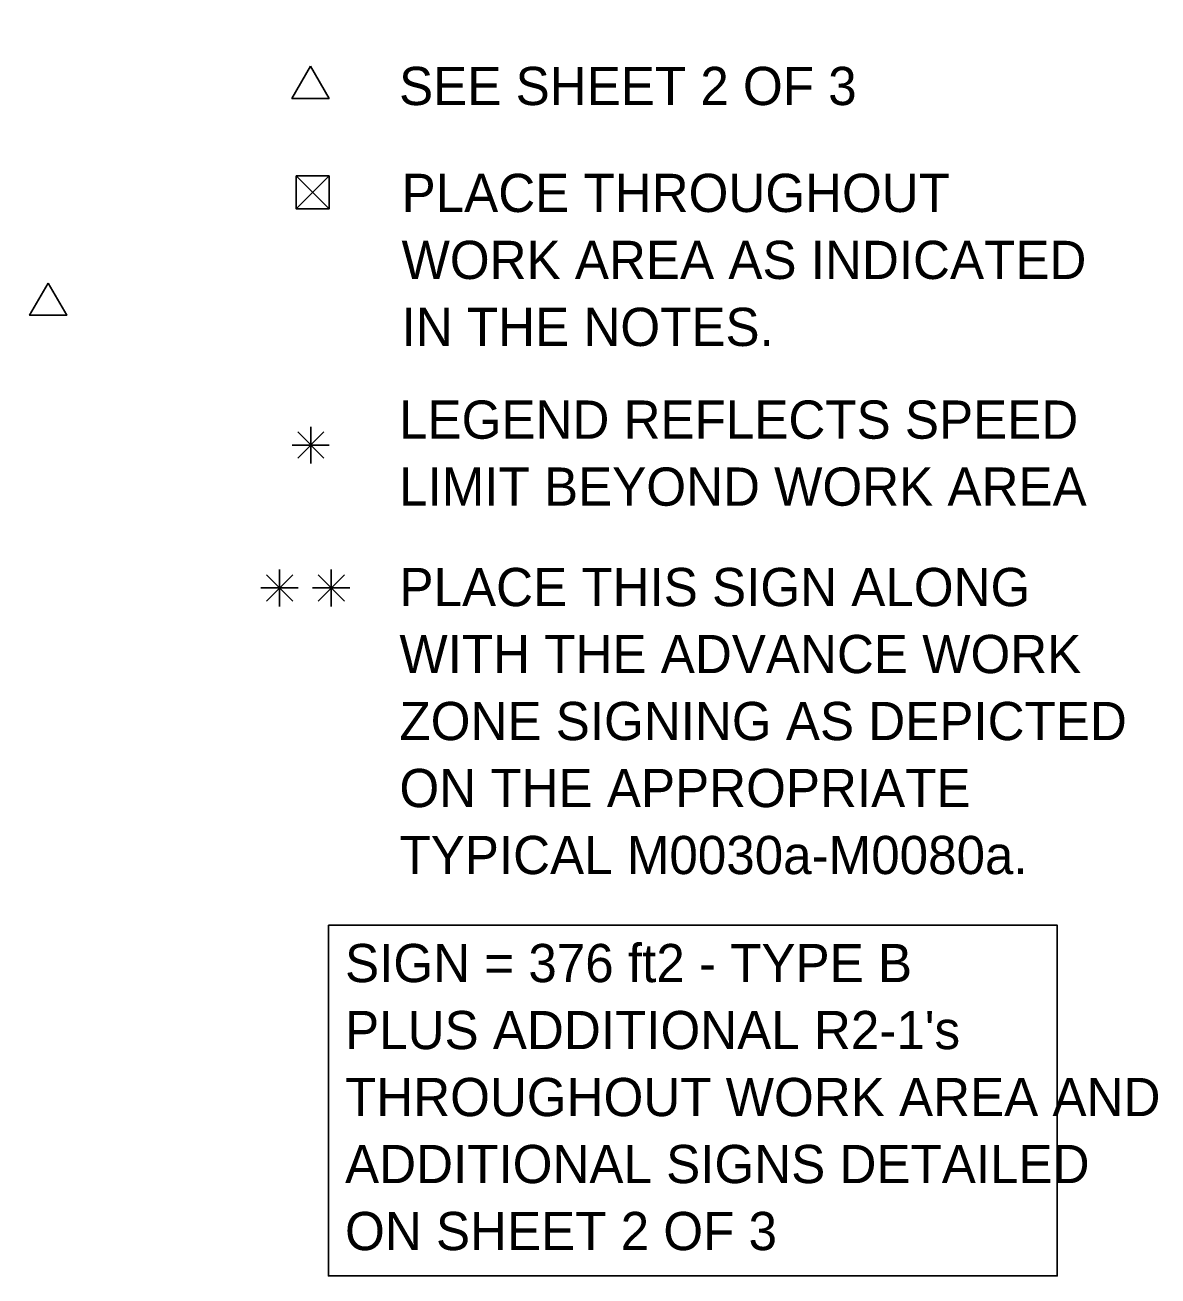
# Model space of a CAD drawing. Extents: x 16728 to 19508, y 5553 to 7079.
# Drawn here: x 17166.3 to 17441.8, y 6180.1 to 6484.5 of the extents above; entities that cross this region are included whole.
import ezdxf

# ---------------------------------------------------------------- set-up
doc = ezdxf.new("R2010")
doc.units = 0
for name, color, linetype in [('PAVT_EDGE_EX', 7, 'Continuous'), ('TYPICAL_TEXT_DIMEN_EX', 7, 'Continuous'), ('TYPICAL_TEXT_DIMEN_PR', 7, 'Continuous')]:
    doc.layers.add(name, color=color, linetype=linetype)

msp = doc.modelspace()

# ---------------------------------------------------------------- linework, layer by layer
at = {"layer": 'PAVT_EDGE_EX'}
for radius in [316, 300]:
    msp.add_arc((17311.82, 6435.06), radius, 105.2177, 180, dxfattribs=at)
at = {"layer": 'TYPICAL_TEXT_DIMEN_EX'}
msp.add_lwpolyline([(17240.08, 6265.46), (17417.36, 6265.46), (17417.36, 6180.14), (17240.08, 6180.14)], close=True, dxfattribs=at)
at = {"layer": 'TYPICAL_TEXT_DIMEN_PR'}
for p, q in [((17232.27, 6447.79), (17240.27, 6439.79)), ((17232.27, 6439.79), (17240.27, 6447.79)), ((17235.83, 6382.33), (17235.83, 6386.79)), ((17232.64, 6385.52), (17239.02, 6379.14)), ((17239.02, 6385.52), (17232.64, 6379.14)), ((17235.83, 6382.33), (17231.3, 6382.33)), ((17235.83, 6382.33), (17239.02, 6382.33)), ((17235.83, 6382.33), (17240.31, 6382.33)), ((17235.83, 6382.33), (17235.83, 6377.83)), ((17225.05, 6350.73), (17231.42, 6344.35)), ((17231.42, 6350.73), (17225.05, 6344.35)), ((17228.24, 6347.54), (17228.24, 6352)), ((17237.6, 6350.73), (17243.98, 6344.35)), ((17243.98, 6350.73), (17237.6, 6344.35)), ((17240.79, 6347.54), (17240.79, 6352)), ((17228.24, 6347.54), (17223.7, 6347.54)), ((17228.24, 6347.54), (17231.42, 6347.54)), ((17228.24, 6347.54), (17232.71, 6347.54)), ((17228.24, 6347.54), (17228.24, 6343.04)), ((17240.79, 6347.54), (17236.26, 6347.54)), ((17240.79, 6347.54), (17243.98, 6347.54)), ((17240.79, 6347.54), (17245.27, 6347.54)), ((17240.79, 6347.54), (17240.79, 6343.04))]:
    msp.add_line(p, q, dxfattribs=at)
for points in [[(17235.74, 6474.5), (17231.22, 6466.67), (17240.27, 6466.67)], [(17232.27, 6447.79), (17232.27, 6439.79), (17240.27, 6439.79), (17240.27, 6447.79)], [(17171.94, 6421.72), (17167.42, 6413.89), (17176.47, 6413.89)]]:
    msp.add_lwpolyline(points, close=True, dxfattribs=at)

# ---------------------------------------------------------------- texts
at = {"layer": 'TYPICAL_TEXT_DIMEN_EX'}
for s, p in [('SEE SHEET 2 OF 3', (17257.28, 6465.04)), ('PLACE THROUGHOUT', (17257.89, 6439.02)), ('WORK AREA AS INDICATED', (17257.89, 6422.72)), ('IN THE NOTES.', (17257.89, 6406.42)), ('LEGEND REFLECTS SPEED', (17257.28, 6383.86)), ('LIMIT BEYOND WORK AREA', (17257.28, 6367.56)), ('PLACE THIS SIGN ALONG', (17257.37, 6343.12)), ('WITH THE ADVANCE WORK', (17257.37, 6326.82)), ('ZONE SIGNING AS DEPICTED', (17257.37, 6310.52)), ('ON THE APPROPRIATE', (17257.37, 6294.22)), ('TYPICAL M0030a-M0080a.', (17257.37, 6277.92)), ('SIGN = 376 ft2 - TYPE B', (17244.14, 6251.63)), ("PLUS ADDITIONAL R2-1's", (17244.14, 6235.33)), ('THROUGHOUT WORK AREA AND', (17244.14, 6219.03)), ('ADDITIONAL SIGNS DETAILED', (17244.14, 6202.73)), ('ON SHEET 2 OF 3', (17244.14, 6186.43))]:
    msp.add_text(s, height=9.3, dxfattribs=at).set_placement(p)

doc.saveas('drawing.dxf')
